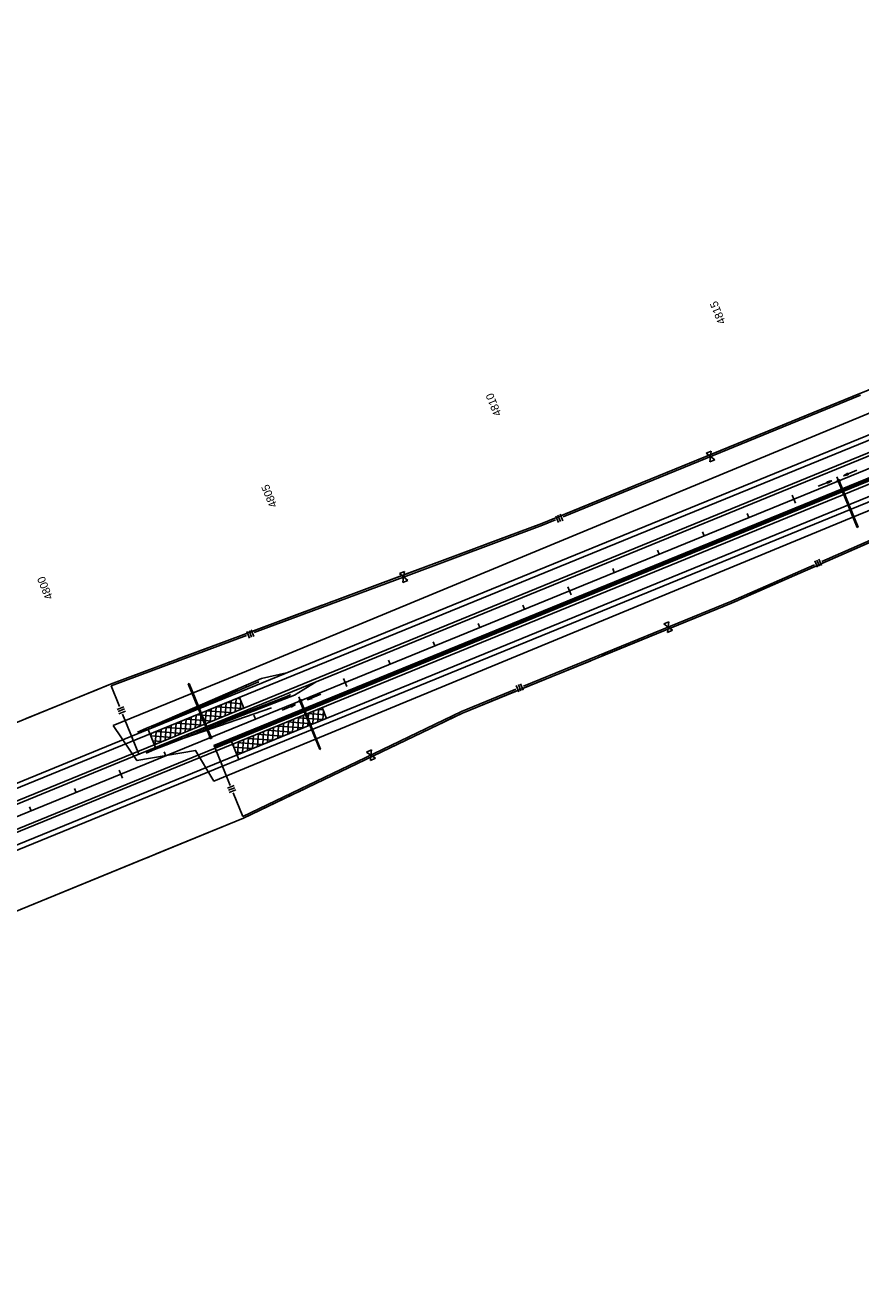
# Model space of a CAD drawing. Extents: x 192699 to 285914, y 194342 to 233219.
# Drawn here: x 226433 to 228157, y 213909 to 216509 of the extents above; entities that cross this region are included whole.
import ezdxf

# ---------------------------------------------------------------- set-up
doc = ezdxf.new("R2010")
doc.units = 0
for name, color, linetype in [('CENT LINE', 7, 'Continuous'), ('CONCRETE', 7, 'Continuous'), ('DRAINAGE', 7, 'Continuous'), ('DRAINAGE ARROWS', 7, 'Continuous'), ('Flood Plain', 7, 'Continuous'), ('GUARDRAIL', 7, 'Continuous'), ('PAVEMENT TRANSITION', 7, 'Continuous'), ('R-W - CofA', 7, 'Continuous'), ('R_Draft', 7, 'Continuous'), ('R_Water Annot', 7, 'Continuous'), ('ROAD', 7, 'Continuous'), ('SHOULDER', 7, 'Continuous'), ('STATIONING1', 7, 'Continuous'), ('WRSF', 7, 'Continuous')]:
    doc.layers.add(name, color=color, linetype=linetype)

msp = doc.modelspace()

# ---------------------------------------------------------------- linework, layer by layer
at = {"layer": 'CENT LINE'}
msp.add_line((219872.3, 212203.9), (229336.9, 216069.6), dxfattribs=at)
at = {"layer": 'CONCRETE'}
for p, q in [((226822.3, 215023.1), (228981.7, 215905.1)), ((226823.9, 215019.4), (228983.2, 215901.3)), ((226823.9, 215019.4), (226822.3, 215023.1))]:
    msp.add_line(p, q, dxfattribs=at)
at = {"layer": 'DRAINAGE'}
for p, q in [((228111.4, 215566.9), (228150, 215472.5)), ((228113.3, 215567.6), (228151.9, 215473.2)), ((226769.2, 215150.5), (226813.9, 215041.2)), ((226771.1, 215151.2), (226815.7, 215042)), ((227000.5, 215113.2), (227040.6, 215015)), ((227002.4, 215113.9), (227042.5, 215015.8))]:
    msp.add_line(p, q, dxfattribs=at)
for points in [[(228110.5, 215566.5), (228114.2, 215568), (228112.7, 215571.7), (228109, 215570.2)], [(226999.6, 215112.8), (227003.3, 215114.3), (227001.8, 215118), (226998.1, 215116.5)], [(226814.4, 215037.2), (226818.1, 215038.7), (226816.6, 215042.4), (226812.9, 215040.9)]]:
    msp.add_lwpolyline(points, close=True, dxfattribs=at)
for points in [[(228150, 215472.5), (228151.9, 215473.2)], [(226769.2, 215150.5), (226771.1, 215151.2)], [(227040.6, 215015), (227042.5, 215015.8)]]:
    msp.add_lwpolyline(points, dxfattribs=at)
at = {"layer": 'DRAINAGE ARROWS'}
for p, q in [((228087.6, 215567), (228097.4, 215569.3)), ((228087.7, 215566.7), (228095.9, 215568.7)), ((228088.6, 215564.4), (228095.9, 215568.7)), ((228088.7, 215564.2), (228097.4, 215569.3)), ((228130.5, 215584.5), (228121.8, 215579.3)), ((228131.6, 215581.7), (228121.8, 215579.3)), ((228130.6, 215584.3), (228123.3, 215579.9)), ((228131.5, 215581.9), (228123.3, 215579.9)), ((228130.7, 215584), (228124.9, 215580.6)), ((228131.4, 215582.2), (228124.9, 215580.6)), ((228130.8, 215583.8), (228126.5, 215581.2)), ((228131.3, 215582.4), (228126.5, 215581.2)), ((228130.9, 215583.6), (228128, 215581.9)), ((228131.2, 215582.7), (228128, 215581.9)), ((228130.9, 215583.3), (228129.6, 215582.5)), ((228131.1, 215582.9), (228129.6, 215582.5)), ((228131.6, 215581.7), (228130.5, 215584.5)), ((228088.7, 215564.2), (228087.6, 215567)), ((228087.8, 215566.5), (228094.3, 215568.1)), ((228087.9, 215566.3), (228092.7, 215567.4)), ((228088, 215566), (228091.2, 215566.8)), ((228088.1, 215565.8), (228089.6, 215566.2)), ((228088.3, 215565.1), (228091.2, 215566.8)), ((228088.3, 215565.4), (228089.6, 215566.2)), ((228088.4, 215564.9), (228092.7, 215567.4)), ((228088.5, 215564.7), (228094.3, 215568.1)), ((226980.8, 215105), (226990.6, 215107.4)), ((226981.9, 215102.3), (226980.8, 215105)), ((226980.9, 215104.8), (226989.1, 215106.8)), ((226981, 215104.6), (226987.5, 215106.1)), ((226981.1, 215104.3), (226985.9, 215105.5)), ((226981.2, 215104.1), (226984.4, 215104.9)), ((226981.3, 215103.9), (226982.8, 215104.3)), ((226981.4, 215103.4), (226982.8, 215104.3)), ((226981.5, 215103.2), (226984.4, 215104.9)), ((226981.6, 215103), (226985.9, 215105.5)), ((226981.7, 215102.7), (226987.5, 215106.1)), ((226981.8, 215102.5), (226989.1, 215106.8)), ((226981.9, 215102.3), (226990.6, 215107.4)), ((227023.6, 215122.6), (227015, 215117.4)), ((227024.8, 215119.8), (227015, 215117.4)), ((227023.7, 215122.3), (227016.5, 215118)), ((227024.7, 215120), (227016.5, 215118)), ((227023.8, 215122.1), (227018.1, 215118.7)), ((227024.6, 215120.3), (227018.1, 215118.7)), ((227023.9, 215121.9), (227019.6, 215119.3)), ((227024.5, 215120.5), (227019.6, 215119.3)), ((227024, 215121.6), (227021.2, 215120)), ((227024.4, 215120.7), (227021.2, 215120)), ((227024.1, 215121.4), (227022.8, 215120.6)), ((227024.3, 215121), (227022.8, 215120.6)), ((227024.8, 215119.8), (227023.6, 215122.6))]:
    msp.add_line(p, q, dxfattribs=at)
at = {"layer": 'Flood Plain'}
for points in [[(230108.2, 216508.6), (226889.4, 215176.3), (226614.2, 215064.2)], [(229548.4, 216068.7), (228137.5, 215493), (226822.4, 214949.9), (226784.5, 215013), (226663.3, 214992.2), (226614.2, 215064.2)]]:
    msp.add_lwpolyline(points, dxfattribs=at)
at = {"layer": 'GUARDRAIL'}
for p, q in [((226692.7, 215059.8), (226872.2, 215138.4)), ((226708.9, 215020.2), (226940.9, 215100.8))]:
    msp.add_line(p, q, dxfattribs=at)
at = {"layer": 'PAVEMENT TRANSITION'}
for p, q in [((226825, 215076), (226826.9, 215102.7)), ((226828, 215103.2), (226882, 215099.3)), ((226835.3, 215080.3), (226837.2, 215107)), ((226845.7, 215084.5), (226847.6, 215111.2)), ((226848.9, 215111.7), (226880.5, 215109.4)), ((226856, 215088.7), (226857.9, 215115.4)), ((226866.3, 215092.9), (226868.2, 215119.6)), ((226869.7, 215120.2), (226876.3, 215119.8)), ((226875.2, 215122.5), (226884.3, 215100.2)), ((226876.6, 215097.1), (226878, 215115.7)), ((227054.9, 215079.2), (227045.8, 215101.4)), ((226763, 215050.7), (226764.9, 215077.4)), ((226765.4, 215077.6), (226819.4, 215073.7)), ((226773.3, 215054.9), (226775.3, 215081.7)), ((226783.7, 215059.2), (226785.6, 215085.9)), ((226786.3, 215086.1), (226840.2, 215082.3)), ((226794, 215063.4), (226795.9, 215090.1)), ((226804.3, 215067.6), (226806.3, 215094.3)), ((226807.1, 215094.7), (226861.1, 215090.8)), ((226814.7, 215071.8), (226816.6, 215098.5)), ((226984.8, 215050.6), (226986.8, 215077.3)), ((226994.3, 215080.4), (227048.2, 215076.5)), ((226995.2, 215054.8), (226997.1, 215081.5)), ((227005.5, 215059), (227007.4, 215085.7)), ((227015.1, 215088.9), (227052, 215086.2)), ((227015.8, 215063.2), (227017.8, 215090)), ((227026.2, 215067.5), (227028.1, 215094.2)), ((227036, 215097.4), (227047.8, 215096.6)), ((227036.5, 215071.7), (227038.4, 215098.4)), ((227046.8, 215075.9), (227048.2, 215095.5)), ((226701, 215025.4), (226703, 215052.1)), ((226702.8, 215052), (226756.7, 215048.2)), ((226711.4, 215029.6), (226713.3, 215056.3)), ((226721.7, 215033.8), (226723.6, 215060.6)), ((226723.7, 215060.6), (226777.6, 215056.7)), ((226732, 215038.1), (226734, 215064.8)), ((226742.4, 215042.3), (226744.3, 215069)), ((226744.5, 215069.1), (226798.5, 215065.2)), ((226752.7, 215046.5), (226754.6, 215073.2)), ((226922.9, 215025.3), (226924.8, 215052)), ((226931.7, 215054.8), (226985.6, 215050.9)), ((226933.2, 215029.5), (226935.1, 215056.2)), ((226943.5, 215033.7), (226945.5, 215060.4)), ((226952.5, 215063.3), (227006.5, 215059.4)), ((226953.9, 215037.9), (226955.8, 215064.6)), ((226964.2, 215042.2), (226966.1, 215068.9)), ((226973.4, 215071.8), (227027.4, 215068)), ((226974.5, 215046.4), (226976.4, 215073.1)), ((226691.7, 215042.8), (226735.9, 215039.6)), ((226692.2, 215041.6), (226692.6, 215047.9)), ((226695.9, 215032.5), (226715, 215031.1)), ((226862.4, 215021.5), (226862.8, 215026.7)), ((226869, 215029.2), (226923, 215025.3)), ((226871.2, 215004.2), (226873.1, 215030.9)), ((226881.6, 215008.4), (226883.5, 215035.1)), ((226889.9, 215037.7), (226943.9, 215033.9)), ((226891.9, 215012.6), (226893.8, 215039.3)), ((226902.2, 215016.8), (226904.1, 215043.5)), ((226910.8, 215046.3), (226964.7, 215042.4)), ((226912.5, 215021.1), (226914.5, 215047.8)), ((226863.2, 215019.6), (226902.1, 215016.8)), ((226867.4, 215009.3), (226881.3, 215008.3))]:
    msp.add_line(p, q, dxfattribs=at)
at = {"layer": 'R-W - CofA'}
for p, q in [((227838.5, 215626), (227848.9, 215630.3)), ((227847.4, 215619.1), (227838.5, 215626)), ((227848.9, 215630.3), (227847.4, 215619.1)), ((227845.9, 215607.9), (227847.4, 215619.1)), ((227856.3, 215612.2), (227845.9, 215607.9)), ((227847.4, 215619.1), (227856.3, 215612.2)), ((227527.9, 215496.4), (227533.3, 215483.1)), ((227532.3, 215498.2), (227537.7, 215484.9)), ((227536.7, 215500), (227542.2, 215486.7)), ((228062.4, 215403.8), (228068, 215390.9)), ((228066.7, 215405.7), (228072.3, 215392.8)), ((228071, 215407.6), (228076.6, 215394.7)), ((227205.1, 215377.9), (227215.7, 215381.9)), ((227213.8, 215370.8), (227205.1, 215377.9)), ((227211.9, 215359.6), (227213.8, 215370.8)), ((227222.5, 215363.6), (227211.9, 215359.6)), ((227215.7, 215381.9), (227213.8, 215370.8)), ((227213.8, 215370.8), (227222.5, 215363.6)), ((226890.5, 215258.2), (226895.5, 215244.7)), ((226895, 215259.8), (226900, 215246.4)), ((226899.5, 215261.5), (226904.5, 215248)), ((227751, 215274.2), (227761.3, 215278.4)), ((227759.8, 215267.5), (227751, 215274.2)), ((227758.3, 215256.5), (227759.8, 215267.5)), ((227768.6, 215260.7), (227758.3, 215256.5)), ((227761.3, 215278.4), (227759.8, 215267.5)), ((227759.8, 215267.5), (227768.6, 215260.7)), ((227446.2, 215147), (227451.6, 215134)), ((227450.6, 215148.8), (227455.9, 215135.7)), ((227454.9, 215150.6), (227460.3, 215137.5)), ((226622.6, 215097.6), (226636, 215102.9)), ((226624.4, 215093.1), (226637.8, 215098.5)), ((226626.2, 215088.7), (226639.5, 215094)), ((227137.2, 215009.7), (227147.2, 215014.5)), ((227146.4, 215003.5), (227137.2, 215009.7)), ((227145.5, 214992.5), (227146.4, 215003.5)), ((227155.5, 214997.2), (227145.5, 214992.5)), ((227147.2, 215014.5), (227146.4, 215003.5)), ((227146.4, 215003.5), (227155.5, 214997.2)), ((226850.4, 214935.3), (226863.8, 214940.7)), ((226852.2, 214930.9), (226865.6, 214936.2)), ((226854, 214926.4), (226867.3, 214931.8))]:
    msp.add_line(p, q, dxfattribs=at)
for points in [[(224081.7, 214063.6), (225192.6, 214517.3), (225555.3, 214687.1), (225729.1, 214790.5), (226608.6, 215149.7), (227499.4, 215481.1), (228702.9, 215972.7), (229243.3, 216236.6)], [(225290.9, 214276.6), (225757.6, 214456.4), (226131.6, 214598.4), (226235.6, 214608.5), (226883.6, 214873.1), (227335.1, 215090), (227890.6, 215316.8), (228257.1, 215477.3), (228812.6, 215704.2), (229386.9, 215884.8)], [(227852.6, 215621.2), (228157, 215745.6)], [(228015.6, 215691.9), (228155.6, 215749.1)], [(227851.2, 215624.8), (227991.2, 215682)], [(227995.7, 215683.8), (228001.1, 215686)], [(228005.6, 215687.9), (228011, 215690.1)], [(227543, 215494.8), (227852.6, 215621.2)], [(227705.9, 215565.5), (227851.2, 215624.8)], [(227541.5, 215498.3), (227681.6, 215555.5)], [(227686.1, 215557.4), (227691.5, 215559.6)], [(228077.2, 215402.7), (228255.7, 215480.8), (228379.3, 215531.3)], [(227384.1, 215438.2), (227499.4, 215481.1), (227525.6, 215491.8)], [(227219.1, 215372.7), (227500.8, 215477.6), (227527, 215488.3)], [(228078.7, 215399.2), (228214.7, 215458.8)], [(227217.7, 215376.3), (227359.5, 215429.1)], [(227364.1, 215430.8), (227369.5, 215432.8)], [(227374.1, 215434.5), (227379.6, 215436.5)], [(227764.9, 215269.6), (227889.1, 215320.3), (228061.7, 215395.9)], [(227927.3, 215332.9), (228063.2, 215392.4)], [(226905.6, 215256.1), (227219.1, 215372.7)], [(227070.7, 215321.6), (227217.7, 215376.3)], [(226904.3, 215259.7), (227046, 215312.4)], [(227050.6, 215314.1), (227056.1, 215316.2)], [(227060.6, 215317.9), (227066.1, 215319.9)], [(227766.3, 215266.1), (227890.6, 215316.8), (227903.6, 215322.5)], [(227908, 215324.5), (227913.3, 215326.8)], [(227917.6, 215328.7), (227922.9, 215331)], [(227461.1, 215145.5), (227764.9, 215269.6)], [(227623.8, 215207.9), (227766.3, 215266.1)], [(226610.1, 215146.1), (226889.4, 215250.1)], [(226746.3, 215200.9), (226888.1, 215253.7)], [(227614.1, 215203.9), (227619.4, 215206)], [(226580.3, 215138.1), (226608.6, 215149.7), (226721.7, 215191.8)], [(226726.3, 215193.5), (226731.7, 215195.5)], [(226736.3, 215197.2), (226741.8, 215199.2)], [(227462.5, 215142), (227599.9, 215198.1)], [(227604.3, 215199.9), (227609.6, 215202.1)], [(226435, 215078.8), (226580.3, 215138.1)], [(226627.4, 215103.8), (226610.1, 215146.1)], [(227151.4, 215005.9), (227333.6, 215093.4), (227445.4, 215139.1)], [(227310.1, 215077.9), (227335.1, 215090), (227446.8, 215135.6)], [(226654.5, 215037.4), (226633.9, 215087.8)], [(227300.6, 215073.4), (227305.8, 215075.9)], [(227153, 215002.5), (227286.8, 215066.8)], [(227291.1, 215068.8), (227296.3, 215071.3)], [(226882.2, 214876.6), (227151.4, 215005.9)], [(227014.2, 214935.8), (227153, 215002.5)], [(226837.8, 214985.4), (226856, 214940.7)], [(226862.2, 214925.6), (226882.2, 214876.6)], [(226883.6, 214873.1), (226991, 214924.7)], [(226995.3, 214926.8), (227000.4, 214929.2)], [(227004.7, 214931.3), (227009.9, 214933.8)], [(226703.3, 214799.5), (226883.6, 214873.1)], [(226542, 214733.6), (226679.5, 214789.8)], [(226683.9, 214791.6), (226689.2, 214793.7)], [(226693.6, 214795.5), (226698.9, 214797.7)], [(226399.5, 214675.4), (226542, 214733.6)]]:
    msp.add_lwpolyline(points, dxfattribs=at)
at = {"layer": 'R_Draft'}
for p, q in [((226819.6, 215117.3), (226920.5, 215161.1)), ((226866.9, 215134), (226912.7, 215153.9)), ((226913.9, 215155.5), (226912.7, 215153.9)), ((226914.7, 215153.7), (226912.7, 215153.9)), ((226914.7, 215153.7), (226913.9, 215155.5)), ((226920.5, 215161.1), (226972.1, 215172.9)), ((226988.5, 215126.9), (227033.5, 215154.8)), ((226706.3, 215064.4), (226866.9, 215134)), ((226839.3, 215069.2), (226988.5, 215126.9)), ((226931.3, 215108.5), (226977.9, 215126.6)), ((226979.2, 215128.1), (226977.9, 215126.6)), ((226979.9, 215126.3), (226977.9, 215126.6)), ((226979.2, 215128.1), (226979.9, 215126.3)), ((226704.9, 215067.6), (226819.6, 215117.3)), ((226721.4, 215027.3), (226931.3, 215108.5)), ((226681.8, 215058.1), (226664.5, 215051)), ((226683.2, 215054.9), (226665.8, 215047.7)), ((226681.8, 215058.1), (226705, 215067.6)), ((226683.2, 215054.9), (226706.3, 215064.4)), ((226722.7, 215024.1), (226839.3, 215069.2)), ((226698.3, 215017.8), (226721.4, 215027.3)), ((226699.6, 215014.6), (226722.7, 215024.1)), ((226698.3, 215017.8), (226680.9, 215010.7)), ((226699.6, 215014.6), (226682.3, 215007.5))]:
    msp.add_line(p, q, dxfattribs=at)
for centre in [(226866.6, 215134.7), (226889.5, 215144.7), (226797.8, 215104.9), (226820.7, 215114.8), (226843.6, 215124.8), (226931.6, 215107.8), (226954.9, 215116.9), (226729, 215075), (226751.9, 215085), (226774.8, 215094.9), (226861.6, 215080.8), (226885, 215089.8), (226908.3, 215098.8), (226667, 215049), (226668.4, 215049.6), (226669.9, 215050.2), (226671.3, 215050.8), (226672.8, 215051.4), (226674.2, 215052), (226677.1, 215053.2), (226680, 215054.4), (226682.9, 215055.6), (226688.7, 215057.9), (226706, 215065.1), (226791.7, 215053.7), (226815, 215062.7), (226838.3, 215071.7), (226721.7, 215026.6), (226745, 215035.7), (226768.3, 215044.7), (226682.7, 215010.6), (226684.1, 215011.2), (226685.6, 215011.8), (226687, 215012.4), (226688.4, 215013), (226689.9, 215013.6), (226692.8, 215014.8), (226695.7, 215016), (226698.6, 215017.1), (226704.3, 215019.5)]:
    msp.add_circle(centre, 0.75, dxfattribs=at)
at = {"layer": 'R_Water Annot'}
for p, q in [((228069.6, 215558), (228097.4, 215569.3)), ((228087.6, 215567), (228097.4, 215569.3)), ((228087.7, 215566.7), (228095.9, 215568.7)), ((228088.6, 215564.4), (228095.9, 215568.7)), ((228088.7, 215564.2), (228097.4, 215569.3)), ((228149.5, 215590.7), (228121.8, 215579.3)), ((228130.5, 215584.5), (228121.8, 215579.3)), ((228131.6, 215581.7), (228121.8, 215579.3)), ((228130.6, 215584.3), (228123.3, 215579.9)), ((228131.5, 215581.9), (228123.3, 215579.9)), ((228130.7, 215584), (228124.9, 215580.6)), ((228131.4, 215582.2), (228124.9, 215580.6)), ((228130.8, 215583.8), (228126.5, 215581.2)), ((228131.3, 215582.4), (228126.5, 215581.2)), ((228130.9, 215583.6), (228128, 215581.9)), ((228131.2, 215582.7), (228128, 215581.9)), ((228130.9, 215583.3), (228129.6, 215582.5)), ((228131.1, 215582.9), (228129.6, 215582.5)), ((228131.6, 215581.7), (228130.5, 215584.5)), ((228088.7, 215564.2), (228087.6, 215567)), ((228087.8, 215566.5), (228094.3, 215568.1)), ((228087.9, 215566.3), (228092.7, 215567.4)), ((228088, 215566), (228091.2, 215566.8)), ((228088.1, 215565.8), (228089.6, 215566.2)), ((228088.3, 215565.1), (228091.2, 215566.8)), ((228088.3, 215565.4), (228089.6, 215566.2)), ((228088.4, 215564.9), (228092.7, 215567.4)), ((228088.5, 215564.7), (228094.3, 215568.1)), ((227042.7, 215128.8), (227015, 215117.4)), ((226962.8, 215096.1), (226990.6, 215107.4)), ((226980.8, 215105), (226990.6, 215107.4)), ((226981.9, 215102.3), (226980.8, 215105)), ((226980.9, 215104.8), (226989.1, 215106.8)), ((226981, 215104.6), (226987.5, 215106.1)), ((226981.1, 215104.3), (226985.9, 215105.5)), ((226981.2, 215104.1), (226984.4, 215104.9)), ((226981.3, 215103.9), (226982.8, 215104.3)), ((226981.4, 215103.4), (226982.8, 215104.3)), ((226981.5, 215103.2), (226984.4, 215104.9)), ((226981.6, 215103), (226985.9, 215105.5)), ((226981.7, 215102.7), (226987.5, 215106.1)), ((226981.8, 215102.5), (226989.1, 215106.8)), ((226981.9, 215102.3), (226990.6, 215107.4)), ((227023.6, 215122.6), (227015, 215117.4)), ((227024.8, 215119.8), (227015, 215117.4)), ((227023.7, 215122.3), (227016.5, 215118)), ((227024.7, 215120), (227016.5, 215118)), ((227023.8, 215122.1), (227018.1, 215118.7)), ((227024.6, 215120.3), (227018.1, 215118.7)), ((227023.9, 215121.9), (227019.6, 215119.3)), ((227024.5, 215120.5), (227019.6, 215119.3)), ((227024, 215121.6), (227021.2, 215120)), ((227024.4, 215120.7), (227021.2, 215120)), ((227024.1, 215121.4), (227022.8, 215120.6)), ((227024.3, 215121), (227022.8, 215120.6)), ((227024.8, 215119.8), (227023.6, 215122.6))]:
    msp.add_line(p, q, dxfattribs=at)
at = {"layer": 'ROAD'}
for p, q in [((210661.6, 208500.3), (229316.5, 216119.6)), ((210670.7, 208478.1), (229325.6, 216097.4)), ((219316.1, 211944.3), (229348.3, 216041.8)), ((210702.4, 208400.3), (229357.4, 216019.6)), ((226652.5, 215042.3), (226686.3, 215056.1)), ((226686.3, 215056.1), (226701.4, 215019.1)), ((225624.9, 214622.6), (226665.8, 215047.7)), ((226824.6, 215017.6), (226858.4, 215031.4)), ((226873.5, 214994.3), (226858.4, 215031.4)), ((225640, 214585.6), (226680.9, 215010.7)), ((225783.7, 214592.4), (226824.6, 215017.6)), ((226667.6, 215005.3), (226701.4, 215019.1)), ((225798.8, 214555.4), (226839.7, 214980.5)), ((226839.7, 214980.5), (226873.5, 214994.3))]:
    msp.add_line(p, q, dxfattribs=at)
for points in [[(226652.5, 215042.3), (226667.6, 215005.3)], [(226839.7, 214980.5), (226824.6, 215017.6)]]:
    msp.add_lwpolyline(points, dxfattribs=at)
at = {"layer": 'SHOULDER'}
for p, q in [((226686.3, 215056.1), (229312.7, 216128.8)), ((226701.4, 215019.1), (229327.9, 216091.8)), ((226858.4, 215031.4), (229346, 216047.4)), ((226873.5, 214994.3), (229361.1, 216010.3))]:
    msp.add_line(p, q, dxfattribs=at)
at = {"layer": 'STATIONING1'}
for points in [[(228108.2, 215577.5), (228111.6, 215569.1)], [(228015.6, 215539.6), (228022.4, 215523)], [(227923.1, 215501.8), (227926.5, 215493.5)], [(227830.5, 215464), (227833.9, 215455.7)], [(227737.9, 215426.2), (227741.3, 215417.9)], [(227645.3, 215388.4), (227648.7, 215380.1)], [(227552.7, 215350.6), (227559.6, 215333.9)], [(227460.2, 215312.8), (227463.6, 215304.4)], [(227367.6, 215275), (227371, 215266.6)], [(227275, 215237.2), (227278.4, 215228.8)], [(227182.4, 215199.3), (227185.8, 215191)], [(227089.9, 215161.5), (227096.7, 215144.9)], [(226997.3, 215123.7), (227000.7, 215115.4)], [(226904.7, 215085.9), (226908.1, 215077.6)], [(226812.1, 215048.1), (226815.5, 215039.8)], [(226719.6, 215010.3), (226723, 215002)], [(226627, 214972.5), (226633.8, 214955.8)], [(226534.4, 214934.7), (226537.8, 214926.3)], [(226441.8, 214896.9), (226445.2, 214888.5)]]:
    msp.add_lwpolyline(points, dxfattribs=at)
at = {"layer": 'WRSF'}
msp.add_line((226823.1, 215021.3), (228982.4, 215903.2), dxfattribs=at)

# ---------------------------------------------------------------- texts
at = {"layer": 'STATIONING1'}
for s, p in [('4815', (227879, 215895.9)), ('4810', (227416.4, 215706.2)), ('4805', (226953.3, 215517.8)), ('4800', (226490.6, 215328.1))]:
    msp.add_text(s, height=16.5, rotation=112.2167, dxfattribs=at).set_placement(p)

doc.saveas('drawing.dxf')
